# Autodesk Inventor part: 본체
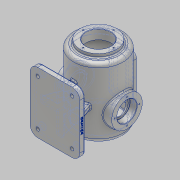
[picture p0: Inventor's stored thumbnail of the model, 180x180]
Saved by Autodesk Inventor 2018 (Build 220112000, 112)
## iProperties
Created: 2021-11
Part Number: 본체
Material: 알루미늄 6061
Document SubType Name: Modeling
Designer: home
Density: 2.7 g/cm^3
Appearance: 알루미늄 - 평지
Mass: 3540.54 g
Surface Area: 2404.16 cm^2
Volume: 1311.31 cm^3
Author: home
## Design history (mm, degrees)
sketch "스케치1"
  geometry: L1 (-45, -80)-(45, -80); L2 (65, -60)-(65, 60); L3 (45, 80)-(-45, 80); L4 (-65, 60)-(-65, -60); L5 (-65, -80)-(65, 80); L6 (65, -80)-(-65, 80); A1 r 20 centre (45, 60) between (65, 60) and (45, 80); A2 r 20 centre (45, -60) between (45, -80) and (65, -60); A3 r 20 centre (-45, -60) between (-65, -60) and (-45, -80); A4 r 20 centre (-45, 60) between (-45, 80) and (-65, 60); 1 further point
  constraints: 12 end point, 8 point on circle, 8 point on line, 8 tangent, 4 centre point, 3 equal radius, 2 midpoint, 2 parallel, 1 horizontal, 1 perpendicular
  dimensions: "d0" = 130 distance of L6.end L5.end; "d1" = 160 distance of L5.end L6.start; "d2" = 20 radius of A1
extrude "돌출1" new body sketch "스케치1" distance "d4" = 14; taper "d5" = 0 deg
sketch "스케치2"
  geometry: L1 (-45, -80)-(45, -80) reference; A1 r 20 centre (-45, -60) between (-65, -60) and (-45, -80) reference; A2 r 20 centre (45, -60) between (45, -80) and (65, -60) reference; A3 r 20 centre (45, 60) between (65, 60) and (45, 80) reference; A4 r 20 centre (-45, 60) between (-45, 80) and (-65, 60) reference; 1 further point
hole "구멍1" sketch "스케치2" at (-45, -60), (45, -60), (-45, 60), (45, 60) diameter "d6" = 9; stored, may be unused: countersink angle "d10" = 90 deg, drill point angle "d12" = 118 deg; dims "d7" = 6, "d8" = 18, "d9" = 2, "d11" = 8
node "작업 평면1"
sketch "스케치3"
  geometry: L1 (0, -80)-(0, -110); L2 (-47.5, -110)-(-47.5, -100); L3 (-47.5, -100)-(-55, -100); L4 (-65, -90)-(-65, 71.239); L5 (0, -110)-(0, 100); L6 (-47.5, -110)-(-32.5, -110); L7 (-32.5, -110)-(-32.5, -85); L8 (-32.5, -85)-(-52, -85); L9 (-55, -82)-(-55, 69.75); A1 r 100 centre (0, 0) between (0, 100) and (-61.111, 79.154); A2 r 90 centre (0, 0) between (0, 90) and (-53.793, 72.155); A3 r 10 centre (-55, -90) between (-65, -90) and (-55, -100); A4 r 10 centre (-55, 71.239) between (-61.111, 79.154) and (-65, 71.239); A5 r 3 centre (-52, 69.75) between (-53.793, 72.155) and (-55, 69.75); A6 r 3 centre (-52, -82) between (-55, -82) and (-52, -85); 5 further points
  constraints: 18 end point, 14 point on circle, 9 tangent, 7 point on line, 6 centre point, 4 vertical, 2 coincident, 2 equal radius, 2 parallel, 2 perpendicular, 1 horizontal
  dimensions: "d14" = 30 distance of L1.start L1.end; "d15" = 47.5 distance of L1.end L2.start; "d16" = 10 distance of L2.start L2.end; "d17" = 17.5 distance of L2.end point (-65, -100); "d23" = 200 diameter of A1; "d24" = 210 distance of L5.end L1.end; "d26" = 32.5 distance of L1.end L6.end; "d27" = 25 distance of L6.end L7.end; "d28" = 22.5 distance of L7.end point (-55, -85); "d29" = 180 diameter of A2; "d30" = 0 distance from line of point (0, 0) L1; "d32" = 10 radius of A3; "d33" = 3 radius of A5
revolve "회전1" sketch "스케치3" stored, may be unused: angle "d31" = 90 deg
node "작업 평면2"
sketch "스케치6"
  geometry: L1 (-47.5, 100.62)-(47.5, 100.62) reference; L2 (0, 100.62)-(0, -26.38); C1 r 40 at (0, -26.38); 1 further point
  constraints: 2 end point, 1 centre point, 1 coincident, 1 midpoint, 1 vertical
  dimensions: "d40" = 127 distance of L2.start L2.end; "d41" = 80 diameter of C1
extrude "돌출2" join sketch "스케치6" stored distance "d42" = 0; taper "d43" = 0 deg
sketch "스케치7"
  geometry: C1 r 40 at (26.38, 0); A1 r 40 centre (26.38, 0) between (66.38, 0) and (-13.62, 0) reference; 1 further point
  constraints: 1 centre point, 1 coincident
  dimensions: "d44" = 80 diameter of C1
extrude "돌출3" join sketch "스케치7" distance "d45" = 10; taper "d46" = 0 deg
hole "구멍2" diameter "d49" = 52; stored, may be unused: countersink angle "d53" = 90 deg, drill point angle "d55" = 0 deg; dims "d47" = 10, "d48" = 10, "d50" = 6, "d51" = 52, "d52" = 18, "d54" = 18
hole "구멍3" diameter "d58" = 42; stored, may be unused: countersink angle "d62" = 90 deg, drill point angle "d64" = 0 deg; dims "d56" = 10, "d57" = 10, "d59" = 6, "d60" = 52, "d61" = 18, "d63" = 18
node "작업 평면3"
sketch "스케치8"
  geometry: L1 (47.5, -110)-(-47.5, -110) reference; L2 (0, -110)-(0, -60); L3 (0, -60)-(-15, -60); L4 (-30, -45)-(-30, 45); L5 (55, 69.75)-(-55, 69.75) reference; L6 (-15, 60)-(15, 60); L7 (30, 45)-(30, -45); L8 (15, -60)-(0, -60); A1 r 15 centre (-15, -45) between (-30, -45) and (-15, -60); A2 r 15 centre (15, -45) between (15, -60) and (30, -45); A3 r 15 centre (15, 45) between (30, 45) and (15, 60); A4 r 15 centre (-15, 45) between (-15, 60) and (-30, 45); 5 further points
  constraints: 12 end point, 8 point on circle, 8 point on line, 8 tangent, 4 centre point, 3 equal radius, 3 perpendicular, 1 horizontal, 1 midpoint, 1 vertical
  dimensions: "d66" = 50 distance of L2.start L2.end; "d67" = 30 distance of L2.end point (-30, -60); "d68" = 120 distance of point (-30, -60) point (-30, 60); "d70" = 60 distance of point (-30, 60) point (30, 60); "d71" = 120 distance of point (30, 60) point (30, -60); "d72" = 15 radius of A1
extrude "돌출4" join sketch "스케치8" stored distance "d73" = 10; taper "d74" = 0 deg
sketch "스케치9"
  geometry: L1 (-20, -45)-(-20, 45); L2 (-15, 50)-(15, 50); L3 (-15, -50)-(15, -50); L4 (20, -45)-(20, 45); L5 (-30, 45)-(-30, -45) reference; L6 (30, -45)-(30, 45) reference; L7 (-15, -60)-(15, -60) reference; L8 (15, 60)-(-15, 60) reference; A1 r 5 centre (-15, -45) between (-20, -45) and (-15, -50); A2 r 5 centre (15, -45) between (15, -50) and (20, -45); A3 r 5 centre (15, 45) between (20, 45) and (15, 50); A4 r 5 centre (-15, 45) between (-15, 50) and (-20, 45); 1 further point
  constraints: 8 end point, 8 point on circle, 8 tangent, 4 centre point, 3 equal radius, 2 horizontal, 2 vertical
  dimensions: "d75" = 10 distance between parallel lines of L1 L5; "d76" = 10 distance between parallel lines of L6 L4; "d77" = 10 distance between parallel lines of L7 L3; "d78" = 10 distance between parallel lines of L8 L2; "d79" = 5 radius of A1
extrude "돌출5" cut sketch "스케치9" stored distance "d80" = 10; taper "d81" = 0 deg
sketch "스케치10"
  geometry: L1 (-15, -60)-(15, -60) reference; L2 (15, 60)-(-15, 60) reference; L3 (0, -60)-(0, -55); L4 (0, 60)-(0, 55); L5 (0, 0)-(-25, 0); L6 (0, 0)-(25, 0)
  constraints: 8 end point, 2 midpoint, 1 parallel, 1 point on line, 1 vertical
  dimensions: "d82" = 5 distance of L3.start L3.end; "d83" = 5 distance of L4.start L4.end; "d84" = 55 distance of L4.end L5.start (derived); "d85" = 25 distance of L5.start L5.end; "d86" = 25 distance of L5.start L6.end; "d87" = 90 deg angle of L2 L3
hole "구멍4" sketch "스케치10" at (25, 0), (-25, 0), (0, -55), (0, 55) diameter "d88" = 3.242; stored, may be unused: countersink angle "d92" = 90 deg, drill point angle "d94" = 118 deg; dims "d89" = 9, "d90" = 52, "d91" = 18, "d93" = 11
sketch "스케치11"
  geometry: L1 (0, 32.5)-(0, -32.5); L2 (32.5, 0)-(-32.5, 0); C1 r 40 at (0, 0) reference; A1 r 32.5 centre (0, 0) between (0, 32.5) and (0, -32.5); 1 further point
  constraints: 4 end point, 4 point on circle, 1 centre point, 1 coincident, 1 perpendicular, 1 vertical
  dimensions: "d95" = 65 diameter of A1; "d96" = 0 distance from line of C1.centre L2; "d97" = 0 distance from line of C1.centre L1
hole "구멍5" sketch "스케치11" at (0, 32.5), (-32.5, 0), (0, -32.5), (32.5, 0) diameter "d98" = 3.242; stored, may be unused: countersink angle "d102" = 90 deg, drill point angle "d104" = 118 deg; dims "d99" = 11, "d100" = 52, "d101" = 18, "d103" = 13
sketch "스케치12"
  geometry: L1 (0, 40)-(0, -40); L2 (40, 0)-(-40, 0); C1 r 47.5 at (0, 0) reference; A1 r 40 centre (0, 0) between (0, 40) and (0, -40); 1 further point
  constraints: 4 end point, 4 point on circle, 1 centre point, 1 coincident, 1 perpendicular, 1 vertical
  dimensions: "d105" = 80 diameter of A1; "d106" = 0 distance from line of C1.centre L2; "d107" = 0 distance from line of C1.centre L1
hole "구멍6" sketch "스케치12" at (0, 40), (40, 0), (0, -40), (-40, 0) diameter "d108" = 3.242; stored, may be unused: countersink angle "d112" = 90 deg, drill point angle "d114" = 118 deg; dims "d109" = 11, "d110" = 52, "d111" = 18, "d113" = 13
sketch "스케치16"
  geometry: L1 (-50, 14)-(-33.809, 58.485); L2 (65, 0)-(65, 14) reference; L3 (50, 14)-(33.809, 58.485); L4 (-45, 14)-(-65, 14) reference; C1 r 61.111 at (0, 114) reference; A1 r 65 centre (0, 114) between (-33.809, 58.485) and (33.809, 58.485); 2 further points
  constraints: 4 end point, 2 point on circle, 1 centre point, 1 coincident, 1 tangent
  dimensions: "d142" = 15 distance of L2.end L3.start; "d147" = 110 deg angle of L4 L1; "d148" = 20 deg angle of L2 L3; "d149" = 14.09539 distance from line of L2.end L3; "d153" = 115 distance from line of L1.start L2; "d154" = 108.06465 distance from line of L2.end L1
feature "리브3" sketch "스케치16" dims "d155" = 1, "d156" = 14, "d157" = 0, "d158" = 0, "d159" = 1, "d160" = 1
sketch "스케치17"
  geometry: L1 (14, 60)-(14, 80) reference; L2 (14, 80)-(14, 60); L3 (0, -80)-(14, -80) reference; L4 (14, -80)-(14, -60) reference; L5 (14, -80)-(14, -60); L6 (14, -60)-(50.452, -46.733); L7 (14, 60)-(50.852, 46.587); L8 (50.852, 46.587)-(50.452, -46.733); 1 further point
  constraints: 10 end point, 1 collinear, 1 vertical
  dimensions: "d161" = 20 distance of L1.end L1.start (derived); "d162" = 20 distance of L3.end L4.end (derived); "d163" = 110 deg angle of L1 L7; "d164" = 110 deg angle of L4 L6; "d165" = 90.2459 deg angle of L3 L8; "d166" = 36.99529 distance from line of L1.end L8
feature "리브4" sketch "스케치17" dims "d167" = 1, "d168" = 14, "d169" = 0, "d170" = 0, "d171" = 1, "d172" = 1
chamfer "모따기1" distance "d173" = 1; stored, may be unused: second distance "d174" = 2, angle "d175" = 45 deg
fillet "모깎기1" dims "d176" = 0.3, "d177" = 3
sketch "스케치18"
  geometry: L1 (0, 0)-(0, 11) reference; L2 (0, 5.5)-(120, 5.5); L3 (60, 0)-(60, 11); L4 (39.545, 8.353)-(81.024, 8.353); L5 (81.024, 8.353)-(81.024, 2.349); L6 (81.024, 2.349)-(39.545, 2.349); L7 (39.545, 2.349)-(39.545, 8.353)
  constraints: 4 end point, 1 horizontal, 1 midpoint, 1 parallel, 1 vertical, 2 other
  dimensions: "d178" = 81.02373 distance between parallel lines of L1 L5; "d179" = 39.54476 distance between parallel lines of L1 L7; "d180" = 6.00407 distance between parallel lines of L4 L6; "d181" = 2.85328 distance between parallel lines of L2 L4; "d182" = 120 distance from line of L2.end L1; "d183" = 2.64672 distance from line of L3.end L4
feature "엠보싱1" sketch "스케치18" dims "d0" = 130, "d1" = 160, "d2" = 20, "d184" = 0.5, "d185" = 0
node "솔리드1"
mirror "미러1"
mirror "미러2"
mirror "미러3"
